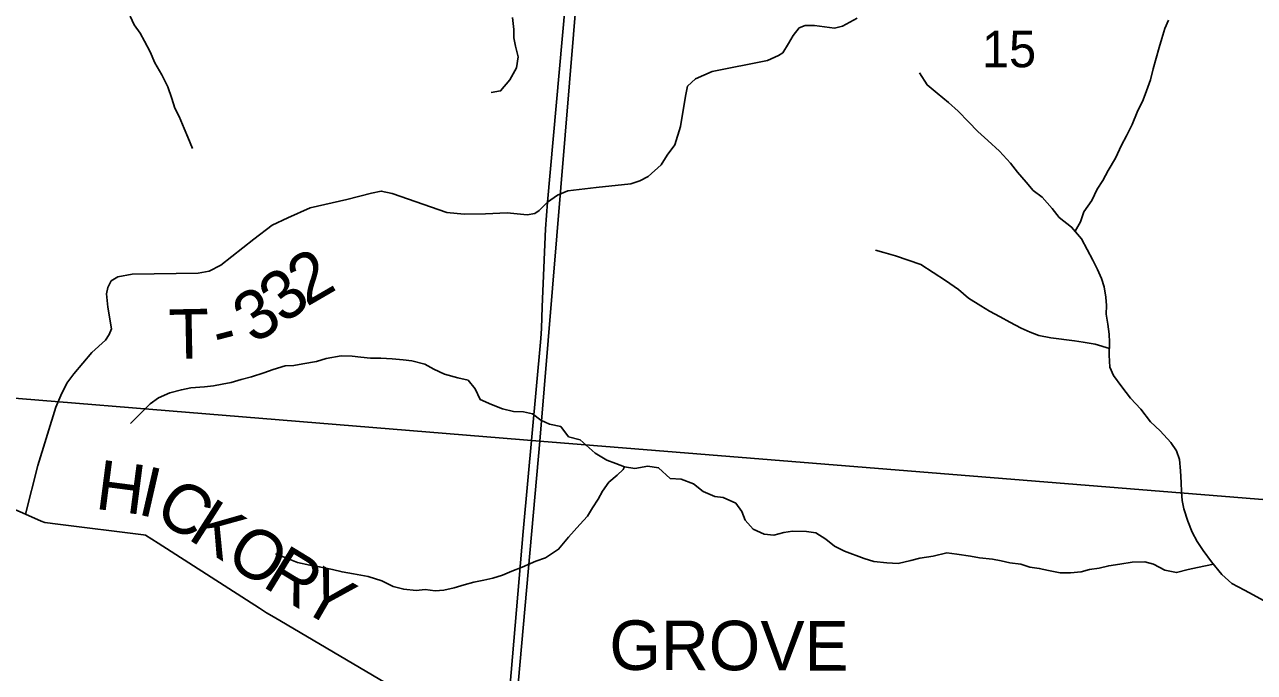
# Model space of a CAD drawing. Extents: x 0 to 42, y 0 to 22.
# Drawn here: x 3.102 to 3.807, y 14.957 to 15.328 of the extents above; entities that cross this region are included whole.
import ezdxf

# ---------------------------------------------------------------- set-up
doc = ezdxf.new("R2010")
doc.units = 0
for name, color, linetype in [('GM_X_County_Road', 7, 'Continuous'), ('GM_X_County_Road_Text', 7, 'Continuous'), ('GM_X_Minor_River', 7, 'Continuous'), ('GM_X_Section', 7, 'Continuous'), ('GM_X_Section_Text', 7, 'Continuous'), ('GM_X_Township_Road', 7, 'Continuous'), ('GM_X_Township_Road_Text', 7, 'Continuous')]:
    doc.layers.add(name, color=color, linetype=linetype)

msp = doc.modelspace()

# ---------------------------------------------------------------- linework, layer by layer
at = {"layer": 'GM_X_County_Road'}
msp.add_lwpolyline([(2.92812, 14.94143), (2.94277, 14.97809), (2.94414, 14.98152), (2.94959, 14.98438), (2.98453, 15.00274), (2.98788, 15.0045), (2.9921, 15.00887), (3.02299, 15.04077), (3.02613, 15.04401), (3.03088, 15.04646), (3.06156, 15.06231), (3.06475, 15.06395), (3.0705, 15.06145), (3.10217, 15.04768), (3.11122, 15.04375), (3.11323, 15.04287), (3.12084, 15.04191), (3.16979, 15.03579), (3.17098, 15.03565), (3.17827, 15.03097), (3.2364, 14.99369), (3.24028, 14.9912), (3.24481, 14.98853), (3.30859, 14.95099)], dxfattribs=at)
at = {"layer": 'GM_X_Minor_River'}
for points in [[(3.16226, 15.33328), (3.16452, 15.32835), (3.1679, 15.3236), (3.17034, 15.31885), (3.17373, 15.31277), (3.17635, 15.30651), (3.1803, 15.29967), (3.18387, 15.29283), (3.18611, 15.286), (3.18779, 15.2805), (3.19023, 15.27575), (3.19324, 15.26891), (3.1953, 15.26398), (3.19792, 15.25733)], [(3.3813, 15.33244), (3.38222, 15.32561), (3.3822, 15.32088), (3.38313, 15.31613), (3.38462, 15.30987), (3.38365, 15.30362), (3.37984, 15.29682), (3.37452, 15.29039), (3.36922, 15.28946)], [(3.70391, 15.20992), (3.707, 15.21532), (3.70892, 15.22099), (3.71348, 15.22761), (3.71653, 15.23404), (3.71977, 15.23895), (3.72282, 15.24481), (3.727, 15.25181), (3.73044, 15.25937), (3.7333, 15.26467), (3.73654, 15.2711), (3.7394, 15.27829), (3.74283, 15.28528), (3.74474, 15.29039), (3.74704, 15.29683), (3.74858, 15.30307), (3.75031, 15.30913), (3.75203, 15.31538), (3.75357, 15.32049), (3.75529, 15.32617), (3.75739, 15.33108)], [(3.81189, 14.9982), (3.80586, 15.00145), (3.80096, 15.00413), (3.79379, 15.00795), (3.78796, 15.01309), (3.78213, 15.02032), (3.77724, 15.02679), (3.77386, 15.03211), (3.77105, 15.03743), (3.76843, 15.0437), (3.7662, 15.05072), (3.76527, 15.05546), (3.76492, 15.06058), (3.76475, 15.06589), (3.76421, 15.07253), (3.76367, 15.07897), (3.76199, 15.0841), (3.7588, 15.08885), (3.75259, 15.09551), (3.74714, 15.10066), (3.7415, 15.10788), (3.73567, 15.11416), (3.73059, 15.12063), (3.7259, 15.12729), (3.72384, 15.13203), (3.72349, 15.13886), (3.72352, 15.14625), (3.72335, 15.15099), (3.72262, 15.15668), (3.7217, 15.16237), (3.72191, 15.1673), (3.72156, 15.17204), (3.72045, 15.17811), (3.71896, 15.18285), (3.71671, 15.18798), (3.71409, 15.1933), (3.71071, 15.19938), (3.70753, 15.20565), (3.70189, 15.21231), (3.69473, 15.21784), (3.69078, 15.22297), (3.68495, 15.22944), (3.67987, 15.23326), (3.67573, 15.23801), (3.67084, 15.24391), (3.6669, 15.24905), (3.6605, 15.2559), (3.65391, 15.262), (3.64808, 15.26714), (3.64281, 15.27266), (3.63679, 15.27875), (3.63133, 15.28371), (3.62474, 15.28904), (3.61909, 15.29381), (3.61459, 15.30084)], [(3.72351, 15.14265), (3.71539, 15.14515), (3.70859, 15.14632), (3.7035, 15.1471), (3.6899, 15.14887), (3.6831, 15.15023), (3.67819, 15.15214), (3.67291, 15.15444), (3.6665, 15.15788), (3.66085, 15.16094), (3.65481, 15.16419), (3.64991, 15.16725), (3.64275, 15.17164), (3.6371, 15.17659), (3.62957, 15.18174), (3.62259, 15.18632), (3.61543, 15.19091), (3.60826, 15.1934), (3.6009, 15.1959), (3.5943, 15.19782), (3.58939, 15.19917)], [(3.42009, 15.09027), (3.41351, 15.09199), (3.40899, 15.09789), (3.40257, 15.09924), (3.39766, 15.10153), (3.39275, 15.10515), (3.38765, 15.10631), (3.38198, 15.10652), (3.37555, 15.10806), (3.36932, 15.11055), (3.3629, 15.11342), (3.35989, 15.11949), (3.35594, 15.12463), (3.35008, 15.12579), (3.34233, 15.1279), (3.33629, 15.13077), (3.33119, 15.13363), (3.32364, 15.13555), (3.31872, 15.13614), (3.31248, 15.13673), (3.30586, 15.13714), (3.3, 15.13716), (3.29452, 15.13775), (3.28941, 15.13834), (3.28317, 15.13855), (3.27465, 15.13688), (3.26897, 15.13519), (3.26121, 15.1339), (3.2561, 15.13297), (3.25099, 15.1328), (3.24417, 15.13074), (3.23887, 15.12868), (3.23167, 15.12643), (3.2258, 15.12494), (3.22012, 15.12325), (3.21501, 15.12232), (3.2099, 15.12121), (3.20479, 15.12066), (3.19704, 15.12012), (3.19155, 15.119), (3.18492, 15.11732), (3.17848, 15.11432), (3.17374, 15.11092), (3.16804, 15.10545), (3.16235, 15.09978)], [(3.78312, 15.01909), (3.77399, 15.01714), (3.76869, 15.01602), (3.76207, 15.01416), (3.75527, 15.01552), (3.74886, 15.01896), (3.74377, 15.02031), (3.73658, 15.02015), (3.72959, 15.01905), (3.72316, 15.01813), (3.71767, 15.01664), (3.71219, 15.0159), (3.70727, 15.0146), (3.70122, 15.01406), (3.69536, 15.01408), (3.68856, 15.01544), (3.68328, 15.0166), (3.67799, 15.01738), (3.67271, 15.01911), (3.66647, 15.01971), (3.66156, 15.02087), (3.65647, 15.02184), (3.6491, 15.02263), (3.644, 15.0236), (3.63607, 15.02478), (3.6304, 15.02556), (3.62246, 15.02351), (3.61489, 15.02241), (3.60978, 15.02111), (3.60241, 15.01943), (3.59598, 15.01984), (3.58843, 15.02063), (3.58296, 15.02218), (3.57163, 15.0264), (3.56598, 15.02927), (3.56108, 15.03327), (3.55524, 15.0369), (3.54995, 15.03768), (3.54183, 15.03791), (3.53691, 15.03717), (3.53123, 15.03568), (3.52557, 15.03627), (3.51934, 15.03914), (3.51483, 15.04428), (3.51277, 15.04922), (3.50939, 15.05397), (3.50223, 15.05723), (3.49731, 15.05782), (3.49071, 15.06069), (3.48506, 15.06508), (3.47808, 15.06776), (3.47185, 15.06817), (3.46507, 15.07427), (3.45903, 15.07524), (3.45146, 15.07395), (3.44561, 15.07492), (3.44052, 15.07684), (3.43542, 15.07857), (3.42882, 15.08258), (3.42009, 15.09027)], [(3.42003, 15.04175), (3.42437, 15.04655), (3.42732, 15.0513), (3.43042, 15.0562), (3.43304, 15.06094), (3.43664, 15.06601), (3.44138, 15.0701), (3.44481, 15.07337), (3.44561, 15.07492)], [(3.42003, 15.04175), (3.41349, 15.03457), (3.40779, 15.02758), (3.4002, 15.02268), (3.39471, 15.0208), (3.38694, 15.01723), (3.38107, 15.01498), (3.37558, 15.01273), (3.37009, 15.01104), (3.36497, 15.00993), (3.3593, 15.00862), (3.35361, 15.00713), (3.34793, 15.00544), (3.34207, 15.00414), (3.33696, 15.00378), (3.33128, 15.00456), (3.32618, 15.00401), (3.31899, 15.00461), (3.31294, 15.00615), (3.30652, 15.00939), (3.29859, 15.01189), (3.29027, 15.01344), (3.28366, 15.0146), (3.27818, 15.01594), (3.27062, 15.01749), (3.26513, 15.01846), (3.25814, 15.02), (3.25153, 15.02268), (3.24549, 15.02498)]]:
    msp.add_lwpolyline(points, dxfattribs=at)
at = {"layer": 'GM_X_Section'}
for points in [[(3.44005, 15.61015), (3.43811, 15.58616), (3.39711, 15.08946), (2.89713, 15.13046), (2.9429, 15.65088)], [(3.93759, 15.55646), (3.89198, 15.04961), (3.39711, 15.08946), (3.43811, 15.58616)], [(2.89713, 15.13046), (3.39711, 15.08946), (3.35135, 14.57775), (2.85743, 14.61911)], [(3.39711, 15.08946), (3.89198, 15.04961), (3.8526, 14.53574), (3.35135, 14.57775)]]:
    msp.add_lwpolyline(points, close=True, dxfattribs=at)
at = {"layer": 'GM_X_Township_Road'}
for points in [[(3.41566, 15.385), (3.41543, 15.38295), (3.41495, 15.37762), (3.40143, 15.22655)], [(3.10217, 15.04768), (3.10924, 15.07551), (3.11958, 15.10911), (3.12239, 15.11569), (3.12592, 15.12274), (3.12991, 15.12814), (3.14025, 15.14036), (3.148, 15.14741), (3.15012, 15.1507), (3.15153, 15.15399), (3.14941, 15.16644), (3.14871, 15.17396), (3.14941, 15.17772), (3.15129, 15.18148), (3.15505, 15.18382), (3.16328, 15.18523), (3.20111, 15.18594), (3.20745, 15.18711), (3.21426, 15.1904), (3.23306, 15.20544), (3.24363, 15.21343), (3.25256, 15.21766), (3.26548, 15.2233), (3.2864, 15.22823), (3.30049, 15.23176), (3.30613, 15.23293), (3.31247, 15.23152), (3.34372, 15.22071), (3.35359, 15.21977), (3.36581, 15.22001), (3.37826, 15.22048), (3.38978, 15.2193), (3.39413, 15.2202), (3.39659, 15.22189), (3.40143, 15.22655), (3.40716, 15.23058), (3.41303, 15.23317), (3.42942, 15.23504), (3.44922, 15.23716), (3.45439, 15.23881), (3.45909, 15.24139), (3.46661, 15.24797), (3.47013, 15.25361), (3.47436, 15.25948), (3.47765, 15.27005), (3.48047, 15.28744), (3.48164, 15.29308), (3.48634, 15.29731), (3.49574, 15.30154), (3.52746, 15.30788), (3.5338, 15.3107), (3.53639, 15.31234), (3.53968, 15.31751), (3.54226, 15.32222), (3.54579, 15.32668), (3.54907, 15.32785), (3.55448, 15.32785), (3.56599, 15.32644), (3.57046, 15.32762), (3.57891, 15.33208)], [(3.40143, 15.22655), (3.40035, 15.21139), (3.39846, 15.16659)], [(3.39846, 15.16659), (3.39793, 15.15414), (3.39769, 15.1484), (3.38753, 15.03772), (3.37992, 14.94791)]]:
    msp.add_lwpolyline(points, dxfattribs=at)

# ---------------------------------------------------------------- texts
at = {"layer": 'GM_X_County_Road_Text'}
for s, height, rotation, p in [('H', 0.02841, 352.62513, (3.14161, 15.05083)), ('I', 0.02841, 347.09782, (3.16569, 15.04775)), ('C', 0.02841, 328.20686, (3.17479, 15.04608)), ('K', 0.02841, 327.45673, (3.19453, 15.03384)), ('O', 0.02841, 327.53191, (3.21564, 15.02037)), ('R', 0.02841, 328.57747, (3.23722, 15.00665)), ('Y', 0.02841, 329.95845, (3.25777, 14.9941)), ('GROVE', 0.028409, 359.80195, (3.43685, 14.95841))]:
    msp.add_text(s, height=height, rotation=rotation, dxfattribs=at).set_placement(p)
at = {"layer": 'GM_X_Section_Text'}
msp.add_text('15', height=0.020928, rotation=0.00001, dxfattribs=at).set_placement((3.65043, 15.30398))
at = {"layer": 'GM_X_Township_Road_Text'}
for s, rotation, p in [('2', 30.17477, (3.26333, 15.1664)), ('3', 38.47221, (3.25052, 15.15612)), ('3', 32.31994, (3.23303, 15.14484)), ('T', 1.1186, (3.18454, 15.13668)), ('-', 14.67756, (3.21303, 15.1381))]:
    msp.add_text(s, height=0.02841, rotation=rotation, dxfattribs=at).set_placement(p)

doc.saveas('drawing.dxf')
